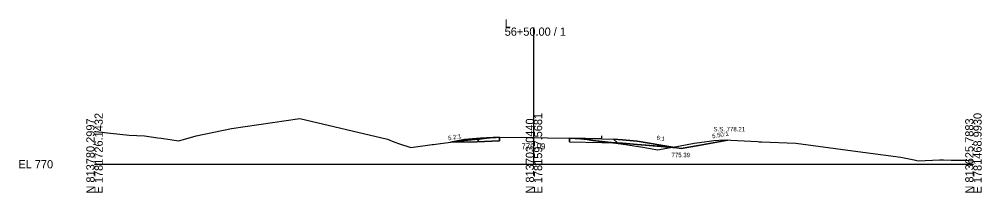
# Model space of a CAD drawing. Extents: x -26 to 7903, y -10 to 9573.
# Drawn here: x 1974.3 to 2302.8, y 7490.3 to 7549.4 of the extents above; entities that cross this region are included whole.
import ezdxf

# ---------------------------------------------------------------- set-up
doc = ezdxf.new("R2010")
doc.units = 0
for name, color, linetype in [('Exist Cross Section Cell', 7, 'Continuous'), ('Exist XS Center Line Elevation Label', 7, 'Continuous'), ('Exist XS Ground Line', 7, 'Continuous'), ('Prop XS Ditch Slope Text', 7, 'Continuous'), ('Prop XS Ditch Standard Text', 7, 'Continuous'), ('Prop XS Dump Level', 7, 'Continuous'), ('Prop XS Earthwork Shape', 7, 'Continuous'), ('Prop XS EOT Tick Mark', 7, 'Continuous'), ('Prop XS Finish Grade', 7, 'Continuous'), ('Prop XS Finish Grade Earthwork', 7, 'Continuous'), ('Prop XS Finish Grade Paved Shoulder', 7, 'Continuous'), ('Prop XS Finish Grade Pavement', 7, 'Continuous'), ('Prop XS Hydro Typical Ditch Data', 7, 'Continuous'), ('Prop XS Pvmt Edge Slope', 7, 'Continuous'), ('Prop XS Side Slope Text', 7, 'Continuous'), ('Prop XS SS Elevation Text', 7, 'Continuous'), ('Prop XS Subgrade Earthwork', 7, 'Continuous'), ('Scratch_Level_3', 7, 'Continuous'), ('Scratch_Level_6', 7, 'Continuous')]:
    doc.layers.add(name, color=color, linetype=linetype)

msp = doc.modelspace()

# ---------------------------------------------------------------- linework, layer by layer
at = {"layer": 'Exist Cross Section Cell'}
for p, q in [((2150, 7500), (2150, 7546.56)), ((2000, 7500), (2150, 7500)), ((2150, 7500), (2300, 7500))]:
    msp.add_line(p, q, dxfattribs=at)
at = {"layer": 'Exist XS Ground Line'}
for p, q in [((2046.78, 7512.13), (2070.11, 7515.52)), ((2070.11, 7515.52), (2100.02, 7508.52)), ((2000, 7511.14), (2000.49, 7511.12)), ((2000.49, 7511.12), (2005.5, 7510.56)), ((2005.5, 7510.56), (2011.86, 7509.94)), ((2034.74, 7509.72), (2046.78, 7512.13)), ((2011.86, 7509.94), (2017.01, 7509.71)), ((2017.01, 7509.71), (2021.59, 7509.02)), ((2021.59, 7509.02), (2022.77, 7508.88)), ((2022.77, 7508.88), (2025.85, 7508.42)), ((2025.85, 7508.42), (2028.72, 7507.98)), ((2028.72, 7507.98), (2030.33, 7508.46)), ((2030.33, 7508.46), (2034.74, 7509.72)), ((2100.02, 7508.52), (2102.19, 7507.68)), ((2102.19, 7507.68), (2104.07, 7506.95)), ((2115.57, 7506.76), (2121.45, 7507.56)), ((2121.45, 7507.56), (2125.03, 7507.98)), ((2125.03, 7507.98), (2132.05, 7508.66)), ((2132.05, 7508.66), (2133.87, 7508.84)), ((2133.87, 7508.84), (2135.02, 7508.96)), ((2135.02, 7508.96), (2137.04, 7509.1)), ((2137.04, 7509.1), (2138.24, 7509.18)), ((2138.24, 7509.18), (2149.66, 7509.09)), ((2149.66, 7509.09), (2150.1, 7509.09)), ((2150.1, 7509.09), (2154.67, 7508.99)), ((2154.67, 7508.99), (2162.09, 7508.84)), ((2162.09, 7508.84), (2165.89, 7508.65)), ((2165.89, 7508.65), (2168.17, 7508.38)), ((2168.17, 7508.38), (2170.08, 7508.14)), ((2170.08, 7508.14), (2177.92, 7507.23)), ((2177.92, 7507.23), (2181.22, 7506.76)), ((2199.29, 7506.16), (2204.63, 7507.14)), ((2204.63, 7507.14), (2206.53, 7507.42)), ((2206.53, 7507.42), (2211.38, 7508.06)), ((2211.38, 7508.06), (2214.96, 7508.28)), ((2214.96, 7508.28), (2226.29, 7507.69)), ((2226.29, 7507.69), (2226.87, 7507.65)), ((2226.87, 7507.65), (2227.66, 7507.62)), ((2227.66, 7507.62), (2239.42, 7507.16)), ((2239.42, 7507.16), (2258.88, 7504.52)), ((2104.07, 7506.95), (2107.96, 7505.75)), ((2107.96, 7505.75), (2115.21, 7506.71)), ((2115.21, 7506.71), (2115.57, 7506.76)), ((2181.22, 7506.76), (2186.43, 7505.93)), ((2186.43, 7505.93), (2189.73, 7505.39)), ((2189.73, 7505.39), (2192.12, 7504.94)), ((2192.12, 7504.94), (2196.59, 7505.7)), ((2196.59, 7505.7), (2198.79, 7506.04)), ((2198.79, 7506.04), (2199.29, 7506.16)), ((2258.88, 7504.52), (2275.2, 7502.45)), ((2275.2, 7502.45), (2277.46, 7501.94)), ((2277.46, 7501.94), (2279.76, 7501.47)), ((2279.76, 7501.47), (2281.09, 7501.18)), ((2281.09, 7501.18), (2288.38, 7501.54)), ((2288.38, 7501.54), (2289.83, 7501.47)), ((2289.83, 7501.47), (2292.38, 7501.34)), ((2292.38, 7501.34), (2296.55, 7501.41)), ((2296.55, 7501.41), (2296.9, 7501.4)), ((2296.9, 7501.4), (2297.36, 7501.4)), ((2297.36, 7501.4), (2298.56, 7501.29)), ((2298.56, 7501.29), (2300, 7501.17))]:
    msp.add_line(p, q, dxfattribs=at)
at = {"layer": 'Prop XS Dump Level'}
for p, q in [((2162.09, 7508.85), (2173.19, 7508.62)), ((2173.19, 7508.62), (2162.09, 7508.85))]:
    msp.add_line(p, q, dxfattribs=at)
at = {"layer": 'Prop XS Earthwork Shape'}
for points in [[(2138.23, 7507.93), (2138.23, 7509.18), (2137.04, 7509.1), (2135.02, 7508.96), (2133.87, 7508.84), (2132.05, 7508.66), (2125.03, 7507.98), (2121.45, 7507.56), (2130.46, 7507.62)], [(2162.09, 7507.59), (2173.19, 7507.37), (2177.19, 7507.28), (2177.53, 7507.28), (2170.08, 7508.14), (2168.17, 7508.38), (2165.89, 7508.65), (2162.09, 7508.84)], [(2177.53, 7507.28), (2177.92, 7507.23), (2181.22, 7506.76), (2186.43, 7505.93), (2189.73, 7505.39), (2192.12, 7504.94), (2196.59, 7505.7), (2197.04, 7505.77), (2185.19, 7506.72), (2180.19, 7507.12), (2178.47, 7507.26)], [(2211.38, 7508.06), (2214.96, 7508.28), (2216.19, 7508.21), (2206.19, 7506.39), (2200.19, 7505.39), (2198.74, 7505.64), (2197.04, 7505.77), (2198.79, 7506.04), (2199.29, 7506.16), (2204.63, 7507.14), (2206.53, 7507.42)]]:
    msp.add_lwpolyline(points, close=True, dxfattribs=at)
at = {"layer": 'Prop XS EOT Tick Mark'}
msp.add_line((2173.19, 7508.62), (2173.19, 7509.62), dxfattribs=at)
at = {"layer": 'Prop XS Finish Grade'}
for p, q in [((2126.23, 7508.48), (2121.45, 7507.56)), ((2131.76, 7508.92), (2126.23, 7508.48)), ((2177.19, 7508.53), (2180.19, 7508.29)), ((2180.19, 7508.29), (2185.19, 7507.89)), ((2185.19, 7507.89), (2198.74, 7505.64))]:
    msp.add_line(p, q, dxfattribs=at)
at = {"layer": 'Prop XS Finish Grade Earthwork'}
for p, q in [((2206.19, 7506.39), (2216.19, 7508.21)), ((2198.74, 7505.64), (2200.19, 7505.39)), ((2200.19, 7505.39), (2206.19, 7506.39))]:
    msp.add_line(p, q, dxfattribs=at)
at = {"layer": 'Prop XS Finish Grade Paved Shoulder'}
msp.add_line((2173.19, 7508.62), (2177.19, 7508.53), dxfattribs=at)
at = {"layer": 'Prop XS Finish Grade Pavement'}
for p, q in [((2138.23, 7509.18), (2131.76, 7508.92)), ((2162.09, 7508.84), (2173.19, 7508.62))]:
    msp.add_line(p, q, dxfattribs=at)
at = {"layer": 'Prop XS Hydro Typical Ditch Data'}
for p, q in [((2185.19, 7507.89), (2200.19, 7505.39)), ((2206.19, 7506.39), (2216.19, 7508.21)), ((2200.19, 7505.39), (2206.19, 7506.39))]:
    msp.add_line(p, q, dxfattribs=at)
at = {"layer": 'Prop XS Pvmt Edge Slope'}
for p, q in [((2131.76, 7508.92), (2130.46, 7507.62)), ((2177.19, 7508.53), (2178.47, 7507.26))]:
    msp.add_line(p, q, dxfattribs=at)
at = {"layer": 'Prop XS Subgrade Earthwork'}
for p, q in [((2130.46, 7507.62), (2121.45, 7507.56)), ((2138.23, 7507.93), (2130.46, 7507.62)), ((2138.23, 7507.93), (2138.23, 7509.18)), ((2162.09, 7507.59), (2162.09, 7508.84)), ((2162.09, 7507.59), (2173.19, 7507.37)), ((2173.19, 7507.37), (2177.19, 7507.28)), ((2177.19, 7507.28), (2178.47, 7507.26)), ((2178.47, 7507.26), (2180.19, 7507.12)), ((2180.19, 7507.12), (2185.19, 7506.72)), ((2185.19, 7506.72), (2198.74, 7505.64))]:
    msp.add_line(p, q, dxfattribs=at)
at = {"layer": 'Scratch_Level_3'}
for p, q in [((2126.23, 7508.48), (2121.45, 7507.56)), ((2121.45, 7507.56), (2130.46, 7507.62)), ((2131.76, 7508.92), (2126.23, 7508.48)), ((2130.46, 7507.62), (2131.76, 7508.92)), ((2180.19, 7508.29), (2177.19, 7508.53)), ((2177.19, 7508.53), (2178.47, 7507.26)), ((2178.47, 7507.26), (2180.19, 7507.12)), ((2185.19, 7507.89), (2180.19, 7508.29)), ((2180.19, 7507.12), (2185.19, 7506.72)), ((2198.74, 7505.64), (2185.19, 7507.89)), ((2185.19, 7506.72), (2198.74, 7505.64))]:
    msp.add_line(p, q, dxfattribs=at)
at = {"layer": 'Scratch_Level_6'}
for points in [[(2138.23, 7507.93), (2130.46, 7507.62), (2121.45, 7507.56), (2125.03, 7507.98), (2132.05, 7508.66), (2133.87, 7508.84), (2135.02, 7508.96), (2137.04, 7509.1), (2138.23, 7509.18)], [(2162.09, 7507.59), (2173.19, 7507.37), (2177.19, 7507.28), (2177.53, 7507.28), (2170.08, 7508.14), (2168.17, 7508.38), (2165.89, 7508.65), (2162.09, 7508.84)], [(2197.5, 7505.84), (2198.74, 7505.64), (2197.04, 7505.77)]]:
    msp.add_lwpolyline(points, close=True, dxfattribs=at)

# ---------------------------------------------------------------- texts
at = {"layer": 'Exist Cross Section Cell'}
for s, p in [('56+50.00 / 1', (2140, 7543.76)), ('L', (2140, 7546.56)), ('EL 770', (1974, 7498.6))]:
    msp.add_text(s, height=2.8, dxfattribs=at).set_placement(p)
for s, p in [('E 1781726.1432', (2002.8, 7490)), ('E 1781597.5681', (2152.8, 7490)), ('E 1781468.9930', (2302.8, 7490)), ('N 813780.2997', (2000, 7490)), ('N 813703.0440', (2150, 7490)), ('N 813625.7883', (2300, 7490))]:
    msp.add_text(s, height=2.8, rotation=90, dxfattribs=at).set_placement(p)
at = {"layer": 'Exist XS Center Line Elevation Label'}
msp.add_text('779.09', height=2, dxfattribs=at).set_placement((2145.73, 7505.09))
at = {"layer": 'Prop XS Ditch Slope Text'}
for s, rotation, p in [('5.2:1', 10.1372, (2120.79, 7508.12)), ('6:1', 350.5377, (2191.74, 7508.32))]:
    msp.add_text(s, height=1.5, rotation=rotation, dxfattribs=at).set_placement(p)
at = {"layer": 'Prop XS Ditch Standard Text'}
msp.add_text('775.39', height=1.5, dxfattribs=at).set_placement((2196.94, 7502.39))
at = {"layer": 'Prop XS Dump Level'}
for s, height, p in [('Eop', 0.3, (2162.09, 7508.54)), ('Case4', 0.04, (2185.19, 7507.85))]:
    msp.add_text(s, height=height, dxfattribs=at).set_placement(p)
at = {"layer": 'Prop XS Side Slope Text'}
msp.add_text('5.50:1', height=1.5, rotation=10.3044, dxfattribs=at).set_placement((2210.92, 7508.78))
at = {"layer": 'Prop XS SS Elevation Text'}
msp.add_text('S.S. 778.21', height=1.5, dxfattribs=at).set_placement((2211.26, 7511.21))

doc.saveas('drawing.dxf')
